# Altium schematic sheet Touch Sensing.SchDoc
size A4; Revision: C.2
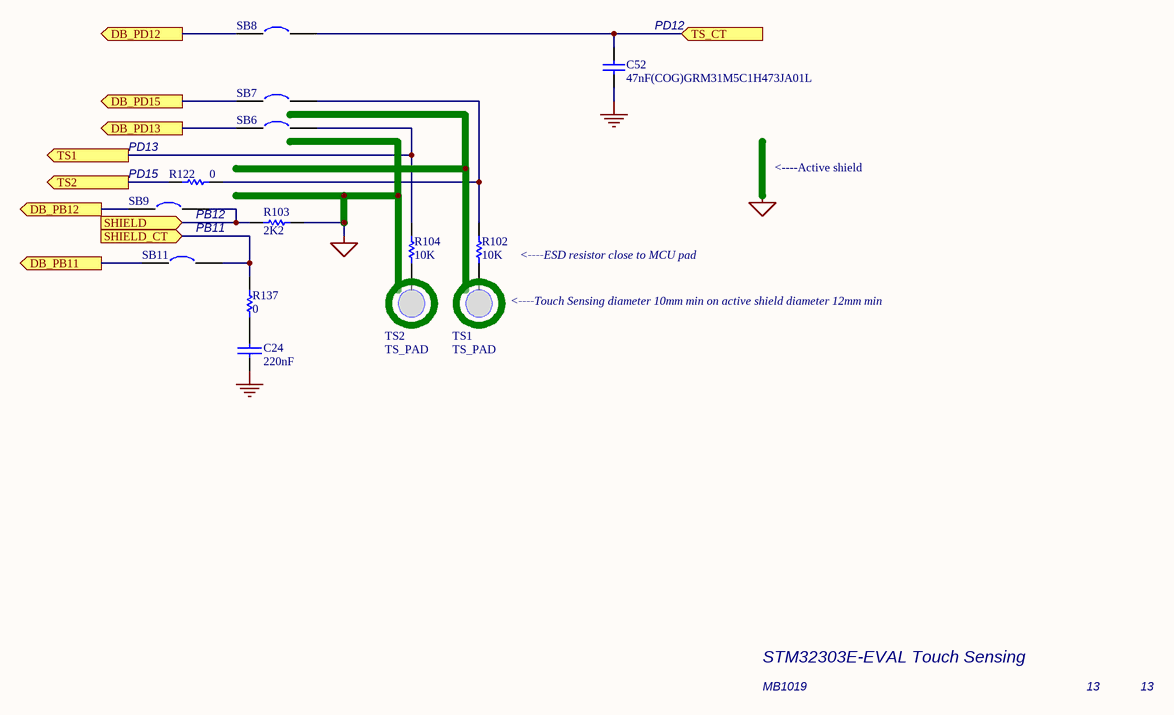
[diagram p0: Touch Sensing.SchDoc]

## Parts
C24  220nF  [0603C]
C52  47nF(COG)GRM31M5C1H473JA01L  [1206C]
R102  10K  [0603R]
R103  2K2  [0603R]
R104  10K  [0603R]
R122  0  [0603R]
R137  0  [0603R]
SB6  (no value)  [JP2_SMD]
SB7  (no value)  [JP2_SMD]
SB8  (no value)  [JP2_SMD]
SB9  (no value)  [JP2_SMD]
SB11  (no value)  [JP2_SMD]
TS1  TS_PAD  [TS_PAD]
TS2  TS_PAD  [TS_PAD]

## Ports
DB_PB11 (out), DB_PB12 (out), DB_PD12 (out), DB_PD13 (out), DB_PD15 (out), SHIELD (in), SHIELD_CT (in), TS1 (out), TS2 (out), TS_CT (in)

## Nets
GND: C24.1 C52.1
TS_SHIELD: R103.2
DB_PB11: SB11.1 ; port DB_PB11
DB_PB12: SB9.1 ; port DB_PB12
DB_PD12: SB8.1 ; port DB_PD12
DB_PD13: SB6.1 ; port DB_PD13
DB_PD15: SB7.1 ; port DB_PD15
SHIELD: R103.1 SB9.2 ; port SHIELD
SHIELD_CT: R137.1 SB11.2 ; port SHIELD_CT
TS1: R104.1 SB6.2 ; port TS1
TS2: R122.2 ; port TS2
TS_CT: C52.2 SB8.2 ; port TS_CT
NetC24_2: C24.2 R137.2
NetR102_1: R102.1 R122.1 SB7.2
NetR102_2: R102.2 TS1.1
NetR104_2: R104.2 TS2.1

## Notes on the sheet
- (near C52) PD12
- PD13
- PD15
- <----Active shield
- (near SB9) PB12
- PB11
- <----ESD resistor close to MCU pad
- <----Touch Sensing diameter 10mm min on active shield diameter 12mm min
- STM32303E-EVAL Touch Sensing
- MB1019
- 13

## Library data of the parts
C24 = CAP: Capacitor
C52 = CAP: Capacitor; Value: 100pF
R102-R104 R122 R137 = Res1: Resistor; Value: 1K
SB6-SB9 SB11 = Circuit Breaker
